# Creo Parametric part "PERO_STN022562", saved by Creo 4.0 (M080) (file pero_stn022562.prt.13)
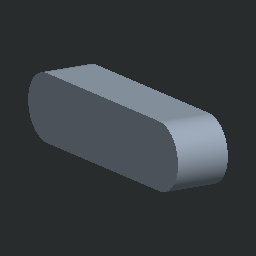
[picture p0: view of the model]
Units: Custom; MM, KILOGRAM, SECS
Materials in the file: OCEL_N

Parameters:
  KATEGORIE = "4"
  HALBZEUG = "."
  NAZOV = "PERO_STN022562"
  N1 = "STN"
  N2 = "TN"
  N3 = "N"
  NAZOV_1 = "START_PART_IPM"
  PTC_MATERIAL_NAME = "OCEL_N"

Other parameters: HMOTNOST, DMIN, DMAX, HUSTOTA, HMOTNOST_1

Created from: STN_022562_PERO.PRT

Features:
  1. datum axis
  2. datum plane "DTM1"

Layers: BEZUGSACHSEN, BEZUGSEBENEN, NORMTEILE

Family table entries: GENERIC, PERO_4X4X8, PERO_STN022562, value(d_val), 2/ , value(i_val), PERO_4X4X10, PERO_STN022562, 2/$, PERO_4X4X12, PERO_STN022562, 2/(, PERO_4X4X14, PERO_STN022562, 2/,, PERO_4X4X16, PERO_STN022562, 2/0, PERO_4X4X18, PERO_STN022562, 2/2, PERO_4X4X20, PERO_STN022562, 2/4, PERO_4X4X22, PERO_STN022562, 2/6, PERO_4X4X25, PERO_STN022562, 2/9, PERO_4X4X28, PERO_STN022562, 2/<, PERO_4X4X32, PERO_STN022562, 2/@, PERO_4X4X36, PERO_STN022562, 2/B, PERO_4X4X40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

Surfaces: 4 plane, 2 cylinder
